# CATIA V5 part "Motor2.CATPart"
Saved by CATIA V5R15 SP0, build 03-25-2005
Part number: Motor2
Bounding box of the stored display mesh (mm): x -25.75 to 25.75, y 266 to 403.5, z -78.549 to -27.069
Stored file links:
  E:\#01 CATIA Lecture Materials\#06 DMU\#11 DMU Page01 KIN EX11\Motor2.CATPart
  E:\V5_education\CATIA Data\KIN\Under Motor\Motor.CATPart
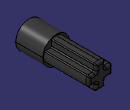
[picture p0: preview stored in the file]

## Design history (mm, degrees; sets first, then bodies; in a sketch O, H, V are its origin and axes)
Parameters
  LENGTH = 2 mm
Body1 "Motor2" (main body)
  Plane1: type Offset, RefPlane zx-plane, Offset 316
  Sketch1 on Plane1, origin (0, 316, 0), H (-1, 0, 0), V (0, 0, 1)
    point P1 (0, -52.8088)
    circle A1 centre (0, -52.8088) radius 25.75
    radius A1 = 25.75
    distance P1 H = 52.8088
    coincidence: P1 V
  Pad1: profile Sketch1, direction (0, 1, 0), length 2, opposite side length 50
  Sketch2 on end face of Pad1, origin (0, 318, 0), H (-1, 0, 0), V (0, 0, 1)
    point P1 (0, -52.8088)
    arc A1 centre (0, -52.8088) radius 23.8 from (0, -29.0088) to (-7.9151, -30.3635) ccw
    line L1 (-20.5591, -43.5588) -> (-11.25, -43.5588)
    line L2 (-9.25, -73.3679) -> (-9.25, -64.0588)
    line L3 (-9.25, -41.5588) -> (-9.25, -32.2497)
    line L4 (-11.25, -62.0588) -> (-20.5591, -62.0588)
    arc A2 centre (0, -52.8088) radius 23.8 from (-22.4453, -44.8937) to (-22.4453, -60.724) ccw
    arc A3 centre (0, -52.8088) radius 23.8 from (-7.9151, -75.2541) to (0, -76.6088) ccw
    point P2 (0, -2.0687)
    construction line L5 (0, -2.0687) -> (0, -8.3393)
    point P3 (0, -29.0088)
    point P4 (0, -76.6088)
    arc A4 centre (-7.25, -73.3679) radius 2 from (-7.9151, -75.2541) to (-9.25, -73.3679) cw
    arc A5 centre (-20.5591, -60.0588) radius 2 from (-22.4453, -60.724) to (-20.5591, -62.0588) ccw
    arc A6 centre (-20.5591, -45.5588) radius 2 from (-22.4453, -44.8937) to (-20.5591, -43.5588) cw
    arc A7 centre (-11.25, -64.0588) radius 2 from (-9.25, -64.0588) to (-11.25, -62.0588) ccw
    arc A8 centre (-11.25, -41.5588) radius 2 from (-11.25, -43.5588) to (-9.25, -41.5588) ccw
    arc A9 centre (-7.25, -32.2497) radius 2 from (-7.9151, -30.3635) to (-9.25, -32.2497) ccw
    point P5 (0, -8.3393)
    point P6 (0, -8.3393)
    point P7 (0, -29.0088)
    point P8 (0, -76.6088)
    point P9 (7.9151, -75.2541)
    point P10 (-7.9151, -75.2541)
    point P11 (9.25, -73.3679)
    point P12 (-9.25, -73.3679)
    point P13 (22.4453, -60.724)
    point P14 (-22.4453, -60.724)
    point P15 (20.5591, -62.0588)
    point P16 (-20.5591, -62.0588)
    point P17 (22.4453, -44.8937)
    point P18 (-22.4453, -44.8937)
    point P19 (20.5591, -43.5588)
    point P20 (-20.5591, -43.5588)
    point P21 (9.25, -64.0588)
    point P22 (-9.25, -64.0588)
    point P23 (11.25, -62.0588)
    point P24 (-11.25, -62.0588)
    point P25 (11.25, -43.5588)
    point P26 (-11.25, -43.5588)
    point P27 (9.25, -41.5588)
    point P28 (-9.25, -41.5588)
    point P29 (7.9151, -30.3635)
    point P30 (-7.9151, -30.3635)
    point P31 (9.25, -32.2497)
    point P32 (-9.25, -32.2497)
    arc A10 centre (0, -52.8088) radius 23.8 from (0, -29.0088) to (7.9151, -30.3635) cw
    line L6 (20.5591, -43.5588) -> (11.25, -43.5588)
    line L7 (9.25, -73.3679) -> (9.25, -64.0588)
    line L8 (9.25, -41.5588) -> (9.25, -32.2497)
    line L9 (11.25, -62.0588) -> (20.5591, -62.0588)
    arc A11 centre (0, -52.8088) radius 23.8 from (22.4453, -44.8937) to (22.4453, -60.724) cw
    arc A12 centre (0, -52.8088) radius 23.8 from (7.9151, -75.2541) to (0, -76.6088) cw
    arc A13 centre (7.25, -73.3679) radius 2 from (7.9151, -75.2541) to (9.25, -73.3679) ccw
    arc A14 centre (20.5591, -60.0588) radius 2 from (22.4453, -60.724) to (20.5591, -62.0588) cw
    arc A15 centre (20.5591, -45.5588) radius 2 from (22.4453, -44.8937) to (20.5591, -43.5588) ccw
    arc A16 centre (11.25, -64.0588) radius 2 from (9.25, -64.0588) to (11.25, -62.0588) cw
    arc A17 centre (11.25, -41.5588) radius 2 from (11.25, -43.5588) to (9.25, -41.5588) cw
    arc A18 centre (7.25, -32.2497) radius 2 from (7.9151, -30.3635) to (9.25, -32.2497) cw
    point P33 (0, 0)
    reference projected circle E1 centre (0, -52.8088) radius 25.75 from edge [face of Pad1 from Sketch1.A1 | end face of Pad1]
    radius A1 = 23.8
    distance L2 L5 = 9.25
    distance L1 L4 = 18.5
    radius A4 = 2 {= Sketch2.radius(A9)}
    radius A5 = 2 {= Sketch2.radius(A9)}
    radius A6 = 2 {= Sketch2.radius(A9)}
    radius A7 = 2 {= Sketch2.radius(A9)}
    radius A8 = 2 {= Sketch2.radius(A9)}
    radius A9 = 2
    coincidence: P1 V, L2 L3, A1 A2, A2 A3, P2 V, L5 P3, L5 P4, P3 P7, P4 P8
    horizontal: L1 H, L4 H
    vertical: L2 V, L3 V, L5 V
    equidistance: L1 L4 P1
    tangency: A4 A3, A4 L2, A5 L4, A5 A2, A6 L1, A6 A2, A7 L2, A7 L4, A8 L1, A8 L3, A9 A1, A9 L3
    symmetry: P6 P5 L5, P3 P7 L5, P4 P8 L5, P10 P9 L5, P12 P11 L5, P14 P13 L5, P16 P15 L5, P18 P17 L5, P20 P19 L5, P22 P21 L5, P24 P23 L5, P26 P25 L5, P28 P27 L5, P30 P29 L5, P32 P31 L5, A1 A10 L5, L1 L6 L5, L2 L7 L5, L3 L8 L5, L4 L9 L5, A2 A11 L5, A3 A12 L5, A4 A13 L5, A5 A14 L5, A6 A15 L5, A7 A16 L5, A8 A17 L5, A9 A18 L5
    concentricity: A10 E1
  Pad2: profile Sketch2, direction (0, 1, 0), length 85.5
  Fillet1: radius 5, on end face of Pad2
